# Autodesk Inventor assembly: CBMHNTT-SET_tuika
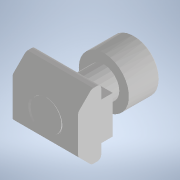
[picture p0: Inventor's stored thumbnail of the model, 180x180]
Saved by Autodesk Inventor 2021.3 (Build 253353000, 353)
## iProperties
Created: 2022-02
Part Number: CBMHNTT-SET_tuika
Document SubType Name: Assembly
Designer: kengo
Author: kengo
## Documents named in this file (3)
- C:\Users\kengo\Documents\S2S_frame\SDC345\frame_misumi_ver12\CBMHNTT-SET_tuika.iam
- C:\Users\kengo\Documents\S2S_frame\SDC345\frame_misumi_ver12\HNTT8-8.ipt
- C:\Users\kengo\Documents\S2S_frame\SDC345\frame_misumi_ver12\CBM8-15.ipt
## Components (2 placed, 2 different names)
1. HNTT8-8:3
2. CBM8-15:3
